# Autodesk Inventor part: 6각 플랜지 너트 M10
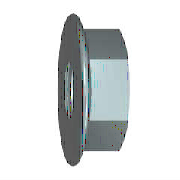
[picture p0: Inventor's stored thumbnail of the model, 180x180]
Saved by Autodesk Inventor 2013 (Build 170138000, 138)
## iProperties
IsCustomPart: 1
Created: 2012-02
Part Number: 6각 플랜지 너트 M10
Material: 강철, 연강
Description: 플랜지붙이 6각 너트
Document SubType Name: Modeling
Standard: JIS B 1190
Designer: mdu-01
Standards Organization: JIS
Language: ko-KR
Size Designation: M 10
Categories: <MemberInstance><Categories><Category DisplayName="조임쇠" InternalName="e4da775c-781d-43d5-af7c-5136215cf5a6" Mnemonic="FSTN"><Category DisplayName="너트" InternalN
Density: 1 g/cm^3
Author: mdu-01
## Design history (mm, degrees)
sketch "스케치1"
  geometry: L1 (-2.276, 0)-(12.046, 0) reference; L2 (3.914, 7)-(2.239, 9.9); L3 (3.914, 7)-(10, 7); L4 (10, 7)-(10, 0); L5 (3.914, 7)-(3.914, 0); L6 (0, -2.152)-(0, 12.911) reference; A1 r 1.2 centre (1.2, 9.3) between (2.239, 9.9) and (0, 9.3); 1 further point
  constraints: 8 end point, 3 point on line, 2 perpendicular, 2 point on circle, 2 tangent, 1 centre point, 1 parallel
  dimensions: "d2" = 14 diameter of L3 L1 (= SW); "d4" = 21 dimension on A1 L1 (= LADI); "d5" = 1.2 radius of A1 (= PHH); "d15" = 10 distance between parallel lines of L4 L6 (= KOH); "d16" = 30 deg angle of L6 L2 (= KEWI)
revolve "링" sketch "스케치1" stored, may be unused: angle "d8" = 90 deg
sketch "스케치2"
  geometry: L1 (-7, -4.041)-(-7, 4.041); L2 (-7, 4.041)-(0, 8.083); L3 (0, 8.083)-(7, 4.041); L4 (7, 4.041)-(7, -4.041); L5 (7, -4.041)-(0, -8.083); L6 (0, -8.083)-(-7, -4.041); C1 r 4.9 at (0, 0); C2 r 9.3 at (0, 0) reference; 1 further point
  constraints: 12 end point, 1 centre point, 1 coincident, 1 vertical, 11 other
  dimensions: "d6" = 16.16581 distance of L5.end L2.end (= 1.1547 x SW)
extrude "본체" join sketch "스케치2" distance "d7" = 10 (= KOH); taper "d9" = 0 deg
sketch "스케치3"
  geometry: L1 (3.288, 8.083)-(10, 8.083) reference; L2 (10, 4.041)-(10, 8.083) reference; L3 (0, -9.3)-(0, 9.3) reference; L4 (-2, 0)-(12, 0) reference; L5 (9.375, 8.083)-(10, 7)
  constraints: 2 end point, 2 point on line
  dimensions: "d10" = 30 deg angle of L2 L5 (= ANG1); "d11" = 14 diameter of L5.end L4 (= SW0)
revolve "모따기1" sketch "스케치3" stored, may be unused: angle "d24" = 90 deg
sketch "스케치4"
  geometry: C1 r 9.3 at (0, 0) reference; 1 further point
  constraints: 1 coincident
hole "스레드" sketch "스케치4" at (0, 0) diameter "d25" = 8.376; stored, may be unused: countersink angle "d29" = 82 deg, drill point angle "d31" = 118 deg; dims "d26" = 6, "d27" = 4, "d28" = 2, "d30" = 8
workaxis "Work Axis1"
workplane "Work Plane1"
body "Solid1"
chamfer "모따기2" distance "d12" = 0.8119 (= -0.5 x GD1 + 0.5 x NND); stored, may be unused: angle "d13" = 30 deg, second distance "d46" = 0.8119 (= -0.5 x GD1 + 0.5 x NND)
chamfer "모따기3" distance "d51" = 0.8119 (= -0.5 x GD1 + 0.5 x NND); stored, may be unused: second distance "d52" = 2, angle "d53" = 45 deg
other parameters: "ANG1" = 30 deg [user parameter; used in 1 equation term], "KEWI" = 30 deg [user parameter; used in 1 equation term], "LADI" = 21 [user parameter; used in 2 equation terms], "SW" = 14 [user parameter; used in 3 equation terms], "PHH" = 1.2 [user parameter; used in 2 equation terms], "KOH" = 10 [user parameter; used in 2 equation terms], "SW0" = 14 [user parameter; used in 1 equation term], "GD1" = 8.3762 (computed from THREADDIA, PTC, TOA) [user parameter; used in 3 equation terms], "d1" = 21 (= LADI), "d3" = 1.2 (= PHH), "d45" = 0, "d47" = 0, "d49" = 0, "d54" = 0, "GUL" = 0.8119 (= 0.541266 x PTC) [user parameter], "TPU" = 6.66667 (computed from PTC) [user parameter], "RR" = 1.4 [user parameter], "TOA" = 30 deg [user parameter; used in 1 equation term], "PTC" = 1.5 [user parameter; used in 4 equation terms], "GAL" = 0.8119 (= 0.541266 x PTC) [user parameter], "E0" = 16.17 (= 1.155 x SW) [user parameter]
